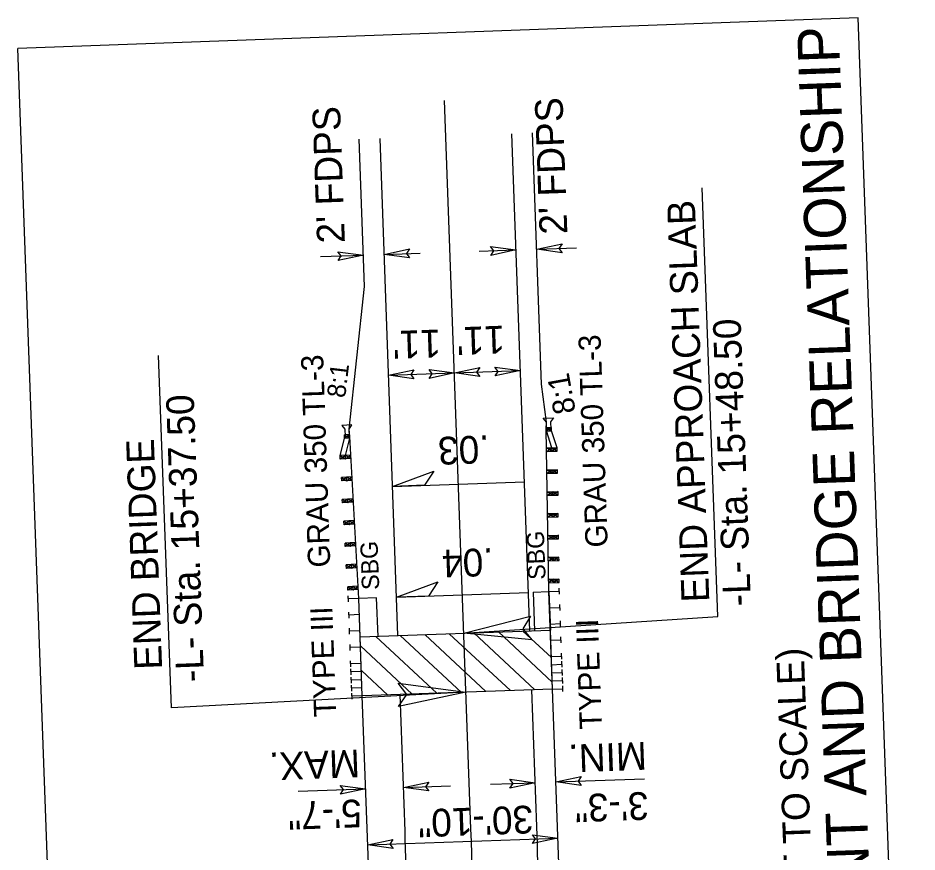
# Model space of a CAD drawing. Extents: x 2065068 to 2066582, y 144283 to 146300.
# Drawn here: x 2065068.5 to 2065327.5, y 145473.9 to 145714.2 of the extents above; entities that cross this region are included whole.
import ezdxf

# ---------------------------------------------------------------- set-up
doc = ezdxf.new("R2010")
doc.units = 0
for name, color, linetype in [('Default', 7, 'Continuous'), ('Prop Approach Slab', 7, 'Continuous'), ('Prop Conc Shoulder Berm Gutter', 7, 'Continuous'), ('Prop Dimension', 7, 'Continuous'), ('Prop Dimension Text', 7, 'Continuous'), ('Prop EOT', 7, 'Continuous'), ('Prop Guardrail Anchor Unit CELL', 7, 'Continuous'), ('Prop Horizontal Alignment', 7, 'Continuous'), ('Prop Paved Shoulder', 7, 'Continuous'), ('Prop Roadway Bridge', 7, 'Continuous'), ('Prop Structure Anchor Unit CELL', 7, 'Continuous'), ('Prop Superelevation  Arrow CELL', 7, 'Continuous'), ('Prop Superelevation Label', 7, 'Continuous'), ('Prop Terminator CELL', 7, 'Continuous')]:
    doc.layers.add(name, color=color, linetype=linetype)

# ---------------------------------------------------------------- blocks, each defined once
blk = doc.blocks.new('Super Arrow Terminator')
at = {"layer": 'Prop Superelevation  Arrow CELL'}
blk.add_lwpolyline([(0, 0), (-6, -2), (-4.625, 0)], close=True, dxfattribs=at)

msp = doc.modelspace()

# ---------------------------------------------------------------- linework, layer by layer
at = {"layer": 'Prop Approach Slab'}
for p, q in [((2065167.07, 145535.87), (2065221.87, 145537.86)), ((2065167.69, 145518.89), (2065167.07, 145535.87)), ((2065189.16, 145519.66), (2065171.56, 145536.04)), ((2065196.23, 145519.92), (2065178.62, 145536.29)), ((2065203.29, 145520.17), (2065185.69, 145536.55)), ((2065210.36, 145520.43), (2065192.76, 145536.8)), ((2065217.43, 145520.68), (2065199.82, 145537.06)), ((2065222.41, 145522.88), (2065206.89, 145537.31)), ((2065222.16, 145529.94), (2065213.96, 145537.57)), ((2065222.48, 145520.87), (2065221.87, 145537.86)), ((2065182.09, 145519.41), (2065167.17, 145533.29)), ((2065175.03, 145519.15), (2065167.42, 145526.23))]:
    msp.add_line(p, q, dxfattribs=at)
at = {"layer": 'Prop Dimension'}
for p, q in [((2065310.61, 145714.2), (2065068.47, 145705.45)), ((2065327.53, 145246.04), (2065310.61, 145714.2)), ((2065085.39, 145237.28), (2065068.47, 145705.45)), ((2065201.4, 145646.99), (2065211.97, 145647.37)), ((2065217.97, 145647.59), (2065229.45, 145648)), ((2065155.61, 145645.45), (2065168, 145645.89)), ((2065173.99, 145646.11), (2065184.39, 145646.49)), ((2065175.25, 145611.26), (2065213.23, 145612.63)), ((2065223.45, 145494.11), (2065248.97, 145495.03)), ((2065149.17, 145491.42), (2065168.65, 145492.13)), ((2065179.54, 145492.52), (2065193.06, 145493.01)), ((2065204.61, 145493.43), (2065217.52, 145493.89)), ((2065169.24, 145475.95), (2065224.04, 145477.93))]:
    msp.add_line(p, q, dxfattribs=at)
for points in [[(2065196.95, 145536.95), (2065270.11, 145541.76), (2065265.64, 145665.24)], [(2065197.56, 145519.97), (2065112.67, 145515.48), (2065109, 145616.96)]]:
    msp.add_lwpolyline(points, dxfattribs=at)
at = {"layer": 'Prop EOT'}
for p, q in [((2065215.94, 145537.64), (2065210.76, 145680.87)), ((2065177.96, 145536.27), (2065172.79, 145679.5)), ((2065217.98, 145481.27), (2065216.55, 145520.65)), ((2065180, 145479.89), (2065178.58, 145519.28))]:
    msp.add_line(p, q, dxfattribs=at)
for radius, start in [(809, 359.19567), (771, 359.05386)]:
    msp.add_arc((2064409.5, 145452.04), radius, start, 2.07024, dxfattribs=at)
at = {"layer": 'Prop Guardrail Anchor Unit CELL'}
for p, q in [((2065219.82, 145598.94), (2065222.76, 145599.05)), ((2065220.72, 145597.8), (2065219.82, 145598.94)), ((2065220.79, 145595.75), (2065220.72, 145597.8)), ((2065222.76, 145599.05), (2065221.94, 145597.84)), ((2065221.94, 145597.84), (2065222.01, 145595.79)), ((2065164.71, 145596.95), (2065161.77, 145596.84)), ((2065161.77, 145596.84), (2065162.67, 145595.7)), ((2065162.67, 145595.7), (2065162.75, 145593.65)), ((2065163.89, 145595.74), (2065164.71, 145596.95)), ((2065163.97, 145593.7), (2065163.89, 145595.74)), ((2065220.71, 145596.22), (2065222.21, 145596.24)), ((2065220.71, 145596.22), (2065222.22, 145595.24)), ((2065221.47, 145548.97), (2065220.71, 145595.72)), ((2065222.21, 145596.24), (2065220.72, 145595.22)), ((2065220.72, 145595.22), (2065222.22, 145595.24)), ((2065222.33, 145590.34), (2065220.72, 145595.22)), ((2065221.4, 145595.77), (2065220.79, 145595.75)), ((2065222.01, 145595.79), (2065221.4, 145595.77)), ((2065222.22, 145595.24), (2065222.21, 145596.24)), ((2065222.22, 145595.24), (2065222.21, 145595.74)), ((2065223.86, 145590.37), (2065222.22, 145595.24)), ((2065161.29, 145588.11), (2065162.58, 145593.09)), ((2065164.02, 145594.17), (2065162.52, 145594.09)), ((2065162.58, 145593.09), (2065162.52, 145594.09)), ((2065162.52, 145594.09), (2065164.08, 145593.17)), ((2065162.58, 145593.09), (2065162.55, 145593.59)), ((2065164.02, 145594.17), (2065162.58, 145593.09)), ((2065164.08, 145593.17), (2065162.58, 145593.09)), ((2065162.75, 145593.65), (2065163.36, 145593.67)), ((2065162.82, 145588.19), (2065164.08, 145593.17)), ((2065163.36, 145593.67), (2065163.97, 145593.7)), ((2065166.67, 145546.99), (2065164.05, 145593.67)), ((2065220.8, 145590.32), (2065223.86, 145590.37)), ((2065222.35, 145589.34), (2065220.8, 145590.32)), ((2065220.82, 145589.32), (2065222.33, 145590.34)), ((2065222.35, 145589.34), (2065222.33, 145590.34)), ((2065222.33, 145590.34), (2065223.88, 145589.37)), ((2065223.86, 145590.37), (2065222.35, 145589.34)), ((2065223.88, 145589.37), (2065223.86, 145590.37)), ((2065164.35, 145588.28), (2065161.29, 145588.11)), ((2065161.35, 145587.11), (2065161.29, 145588.11)), ((2065161.29, 145588.11), (2065162.88, 145587.19)), ((2065162.82, 145588.19), (2065161.35, 145587.11)), ((2065164.41, 145587.28), (2065161.35, 145587.11)), ((2065162.88, 145587.19), (2065162.82, 145588.19)), ((2065164.41, 145587.28), (2065162.82, 145588.19)), ((2065162.88, 145587.19), (2065164.35, 145588.28)), ((2065220.82, 145589.32), (2065223.88, 145589.37)), ((2065220.9, 145584.02), (2065223.9, 145584.07)), ((2065222.42, 145583.04), (2065220.9, 145584.02)), ((2065220.92, 145583.02), (2065222.4, 145584.04)), ((2065220.92, 145583.02), (2065223.92, 145583.07)), ((2065222.42, 145583.04), (2065222.4, 145584.04)), ((2065222.4, 145584.04), (2065223.92, 145583.07)), ((2065223.9, 145584.07), (2065222.42, 145583.04)), ((2065223.92, 145583.07), (2065223.9, 145584.07)), ((2065164.7, 145581.99), (2065161.71, 145581.82)), ((2065161.77, 145580.82), (2065161.71, 145581.82)), ((2065161.71, 145581.82), (2065163.26, 145580.9)), ((2065163.21, 145581.9), (2065161.77, 145580.82)), ((2065164.76, 145580.99), (2065161.77, 145580.82)), ((2065163.26, 145580.9), (2065163.21, 145581.9)), ((2065164.76, 145580.99), (2065163.21, 145581.9)), ((2065163.26, 145580.9), (2065164.7, 145581.99)), ((2065221, 145577.72), (2065224.14, 145577.77)), ((2065222.59, 145576.74), (2065221, 145577.72)), ((2065221.02, 145576.72), (2065222.57, 145577.74)), ((2065222.59, 145576.74), (2065222.57, 145577.74)), ((2065222.57, 145577.74), (2065224.16, 145576.77)), ((2065224.14, 145577.77), (2065222.59, 145576.74)), ((2065224.16, 145576.77), (2065224.14, 145577.77)), ((2065165.06, 145575.69), (2065161.93, 145575.52)), ((2065161.98, 145574.52), (2065161.93, 145575.52)), ((2065161.93, 145575.52), (2065163.55, 145574.61)), ((2065163.49, 145575.61), (2065161.98, 145574.52)), ((2065165.11, 145574.7), (2065161.98, 145574.52)), ((2065163.55, 145574.61), (2065163.49, 145575.61)), ((2065165.11, 145574.7), (2065163.49, 145575.61)), ((2065163.55, 145574.61), (2065165.06, 145575.69)), ((2065221.02, 145576.72), (2065224.16, 145576.77)), ((2065165.41, 145569.4), (2065162.38, 145569.23)), ((2065162.44, 145568.23), (2065162.38, 145569.23)), ((2065162.38, 145569.23), (2065163.95, 145568.32)), ((2065163.9, 145569.32), (2065162.44, 145568.23)), ((2065163.95, 145568.32), (2065163.9, 145569.32)), ((2065165.47, 145568.4), (2065163.9, 145569.32)), ((2065163.95, 145568.32), (2065165.41, 145569.4)), ((2065165.47, 145568.4), (2065165.41, 145569.4)), ((2065221.11, 145571.42), (2065224.14, 145571.47)), ((2065221.12, 145570.42), (2065221.11, 145571.42)), ((2065222.64, 145570.44), (2065221.11, 145571.42)), ((2065221.12, 145570.42), (2065222.62, 145571.44)), ((2065221.12, 145570.42), (2065224.16, 145570.47)), ((2065222.64, 145570.44), (2065222.62, 145571.44)), ((2065222.62, 145571.44), (2065224.16, 145570.47)), ((2065224.14, 145571.47), (2065222.64, 145570.44)), ((2065224.16, 145570.47), (2065224.14, 145571.47)), ((2065165.47, 145568.4), (2065162.44, 145568.23)), ((2065221.21, 145565.12), (2065224.26, 145565.17)), ((2065222.75, 145564.14), (2065221.21, 145565.12)), ((2065221.22, 145564.12), (2065222.73, 145565.14)), ((2065221.22, 145564.12), (2065224.27, 145564.17)), ((2065222.75, 145564.14), (2065222.73, 145565.14)), ((2065222.73, 145565.14), (2065224.27, 145564.17)), ((2065224.26, 145565.17), (2065222.75, 145564.14)), ((2065224.27, 145564.17), (2065224.26, 145565.17)), ((2065165.77, 145563.11), (2065162.72, 145562.94)), ((2065162.78, 145561.94), (2065162.72, 145562.94)), ((2065162.72, 145562.94), (2065164.3, 145562.03)), ((2065164.24, 145563.03), (2065162.78, 145561.94)), ((2065165.82, 145562.11), (2065162.78, 145561.94)), ((2065164.3, 145562.03), (2065164.24, 145563.03)), ((2065165.82, 145562.11), (2065164.24, 145563.03)), ((2065164.3, 145562.03), (2065165.77, 145563.11)), ((2065221.31, 145558.82), (2065224.36, 145558.87)), ((2065222.85, 145557.84), (2065221.31, 145558.82)), ((2065221.33, 145557.82), (2065222.84, 145558.84)), ((2065222.85, 145557.84), (2065222.84, 145558.84)), ((2065222.84, 145558.84), (2065224.38, 145557.87)), ((2065224.36, 145558.87), (2065222.85, 145557.84)), ((2065224.38, 145557.87), (2065224.36, 145558.87)), ((2065166.12, 145556.82), (2065163.07, 145556.65)), ((2065163.13, 145555.65), (2065163.07, 145556.65)), ((2065163.07, 145556.65), (2065164.65, 145555.74)), ((2065164.59, 145556.74), (2065163.13, 145555.65)), ((2065164.65, 145555.74), (2065164.59, 145556.74)), ((2065166.17, 145555.82), (2065164.59, 145556.74)), ((2065164.65, 145555.74), (2065166.12, 145556.82)), ((2065221.33, 145557.82), (2065224.38, 145557.87)), ((2065166.17, 145555.82), (2065163.13, 145555.65)), ((2065221.41, 145552.52), (2065224.41, 145552.56)), ((2065221.41, 145552.52), (2065222.91, 145552.54)), ((2065221.43, 145551.52), (2065221.41, 145552.52)), ((2065222.93, 145551.54), (2065221.41, 145552.52)), ((2065222.91, 145552.54), (2065221.43, 145551.52)), ((2065221.43, 145551.52), (2065224.43, 145551.56)), ((2065222.93, 145551.54), (2065222.91, 145552.54)), ((2065222.91, 145552.54), (2065224.43, 145551.56)), ((2065224.41, 145552.56), (2065222.93, 145551.54)), ((2065224.43, 145551.56), (2065224.41, 145552.56)), ((2065166.47, 145550.53), (2065163.48, 145550.36)), ((2065163.53, 145549.36), (2065163.48, 145550.36)), ((2065163.48, 145550.36), (2065165.03, 145549.45)), ((2065164.97, 145550.45), (2065163.53, 145549.36)), ((2065166.53, 145549.53), (2065163.53, 145549.36)), ((2065166.47, 145550.53), (2065164.97, 145550.45)), ((2065165.03, 145549.45), (2065164.97, 145550.45)), ((2065164.97, 145550.45), (2065166.53, 145549.53)), ((2065165.03, 145549.45), (2065166.47, 145550.53)), ((2065166.53, 145549.53), (2065166.47, 145550.53))]:
    msp.add_line(p, q, dxfattribs=at)
at = {"layer": 'Prop Horizontal Alignment'}
msp.add_line((2065198.99, 145480.58), (2065191.4, 145690.43), dxfattribs=at)
msp.add_arc((2064409.5, 145452.04), 790, 357.89352, 2.07024, dxfattribs=at)
at = {"layer": 'Prop Paved Shoulder'}
for p, q in [((2065219.37, 145608.74), (2065216.76, 145681.09)), ((2065168.32, 145636.87), (2065166.79, 145679.28)), ((2065163.89, 145595.74), (2065168.32, 145636.87)), ((2065220.72, 145597.8), (2065219.37, 145608.74)), ((2065220.71, 145595.72), (2065220.72, 145597.8)), ((2065164.05, 145593.67), (2065163.89, 145595.74)), ((2065221.47, 145548.97), (2065220.71, 145595.72)), ((2065166.67, 145546.99), (2065164.05, 145593.67)), ((2065216.88, 145548.81), (2065221.47, 145548.97)), ((2065216.88, 145548.81), (2065217.28, 145537.69)), ((2065221.47, 145548.97), (2065221.87, 145537.86)), ((2065171.81, 145547.18), (2065166.67, 145546.99)), ((2065167.07, 145535.87), (2065166.67, 145546.99)), ((2065172.21, 145536.06), (2065171.81, 145547.18))]:
    msp.add_line(p, q, dxfattribs=at)
at = {"layer": 'Prop Roadway Bridge'}
for p, q in [((2065222.48, 145520.87), (2065167.69, 145518.89)), ((2065225.37, 145440.94), (2065222.48, 145520.87)), ((2065170.58, 145438.96), (2065167.69, 145518.89))]:
    msp.add_line(p, q, dxfattribs=at)
at = {"layer": 'Prop Structure Anchor Unit CELL'}
for p, q in [((2065221.47, 145548.97), (2065224.47, 145549.08)), ((2065222.48, 145520.87), (2065221.47, 145548.97)), ((2065224.5, 145548.22), (2065224.44, 145549.94)), ((2065163.7, 145546.03), (2065163.64, 145547.74)), ((2065166.67, 145546.99), (2065163.67, 145546.88)), ((2065167.69, 145518.89), (2065166.67, 145546.99)), ((2065221.64, 145544.29), (2065224.64, 145544.4)), ((2065224.67, 145543.54), (2065224.6, 145545.26)), ((2065163.87, 145541.34), (2065163.81, 145543.06)), ((2065166.84, 145542.31), (2065163.84, 145542.2)), ((2065164.04, 145536.66), (2065163.98, 145538.37)), ((2065221.81, 145539.6), (2065224.81, 145539.71)), ((2065224.84, 145538.85), (2065224.77, 145540.57)), ((2065167.01, 145537.62), (2065164.01, 145537.52)), ((2065225.01, 145534.17), (2065224.94, 145535.89)), ((2065164.21, 145531.97), (2065164.15, 145533.69)), ((2065167.18, 145532.94), (2065164.18, 145532.83)), ((2065221.98, 145534.92), (2065224.97, 145535.03)), ((2065222.15, 145530.24), (2065225.14, 145530.34)), ((2065225.17, 145529.49), (2065225.11, 145531.2)), ((2065164.38, 145527.29), (2065164.32, 145529)), ((2065167.35, 145528.25), (2065164.35, 145528.15)), ((2065222.23, 145527.89), (2065225.23, 145528)), ((2065225.26, 145527.14), (2065225.2, 145528.86)), ((2065164.47, 145524.95), (2065164.4, 145526.66)), ((2065167.43, 145525.91), (2065164.43, 145525.8)), ((2065222.32, 145525.55), (2065225.31, 145525.66)), ((2065225.34, 145524.8), (2065225.28, 145526.52)), ((2065164.55, 145522.6), (2065164.49, 145524.32)), ((2065167.52, 145523.57), (2065164.52, 145523.46)), ((2065222.4, 145523.21), (2065225.4, 145523.32)), ((2065225.43, 145522.46), (2065225.37, 145524.18)), ((2065164.64, 145520.26), (2065164.57, 145521.98)), ((2065167.6, 145521.23), (2065164.6, 145521.12)), ((2065222.48, 145520.87), (2065225.48, 145520.98)), ((2065225.51, 145520.12), (2065225.45, 145521.83)), ((2065164.72, 145517.92), (2065164.66, 145519.64)), ((2065167.69, 145518.89), (2065164.69, 145518.78))]:
    msp.add_line(p, q, dxfattribs=at)
at = {"layer": 'Prop Superelevation  Arrow CELL'}
for p, q in [((2065176.41, 145579.23), (2065214.39, 145580.6)), ((2065177.56, 145547.33), (2065215.54, 145548.71))]:
    msp.add_line(p, q, dxfattribs=at)
at = {"layer": 'Prop Terminator CELL'}
for points in [[(2065160.67, 145646.88), (2065168, 145645.89), (2065160.72, 145644.33), (2065161.6, 145645.66)], [(2065181.32, 145645.12), (2065173.99, 145646.11), (2065181.27, 145647.67), (2065180.39, 145646.34)], [(2065204.64, 145648.36), (2065211.97, 145647.37), (2065204.69, 145645.81), (2065205.58, 145647.14)], [(2065225.3, 145646.59), (2065217.97, 145647.59), (2065225.25, 145649.15), (2065224.36, 145647.82)], [(2065201.57, 145610.95), (2065194.24, 145611.94), (2065201.52, 145613.5), (2065200.63, 145612.17)], [(2065205.9, 145613.62), (2065213.23, 145612.63), (2065205.95, 145611.07), (2065206.83, 145612.4)], [(2065182.58, 145610.26), (2065175.25, 145611.26), (2065182.53, 145612.82), (2065181.65, 145611.49)], [(2065186.91, 145612.93), (2065194.24, 145611.94), (2065186.96, 145610.38), (2065187.84, 145611.71)], [(2065216.58, 145535.03), (2065196.95, 145536.95), (2065216.19, 145541.83), (2065213.97, 145538.2)], [(2065178.02, 145522.61), (2065197.56, 145519.97), (2065178.15, 145515.81), (2065180.51, 145519.35)], [(2065186.87, 145491.53), (2065179.54, 145492.52), (2065186.82, 145494.08), (2065185.94, 145492.75)], [(2065210.19, 145494.88), (2065217.52, 145493.89), (2065210.24, 145492.33), (2065211.12, 145493.66)], [(2065230.78, 145493.12), (2065223.45, 145494.11), (2065230.73, 145495.67), (2065229.85, 145494.34)], [(2065161.32, 145493.12), (2065168.65, 145492.13), (2065161.38, 145490.57), (2065162.26, 145491.9)], [(2065216.71, 145478.92), (2065224.04, 145477.93), (2065216.76, 145476.37), (2065217.64, 145477.7)], [(2065176.57, 145474.95), (2065169.24, 145475.95), (2065176.52, 145477.51), (2065175.63, 145476.18)]]:
    msp.add_lwpolyline(points, close=True, dxfattribs=at)

# ---------------------------------------------------------------- block references
at = {"layer": 'Prop Superelevation  Arrow CELL', "xscale": 1.999996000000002, "yscale": 1.999996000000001, "rotation": -177.9297555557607}
for p in [(2065176.41, 145579.23), (2065177.56, 145547.33)]:
    msp.add_blockref('Super Arrow Terminator', p, dxfattribs=at)

# ---------------------------------------------------------------- texts
at = {"layer": 'Default'}
for height, rotation, p in [(5.291, 83.1952, (2065162.73, 145604.58)), (6.349, 100.2886, (2065229.23, 145600.67))]:
    msp.add_text('8:1', height=height, rotation=rotation, dxfattribs=at).set_placement(p)
at = {"layer": 'Prop Conc Shoulder Berm Gutter'}
for p in [(2065220.52, 145552.44), (2065172.59, 145549.52)]:
    msp.add_text('SBG', height=5, rotation=92.0702, dxfattribs=at).set_placement(p)
at = {"layer": 'Prop Dimension'}
for s, height, p in [('DETAIL SHOWING PAVEMENT AND BRIDGE RELATIONSHIP', 12, (2065321.51, 145254.04)), ('END APPROACH SLAB', 8, (2065267.69, 145546.01)), ('-L- Sta. 15+48.50', 8, (2065279.68, 145544.83)), ('-L- Sta. 15+37.50', 8, (2065122.1, 145522.98)), ('END BRIDGE', 8, (2065110.02, 145526.58)), ('(NOT TO SCALE)', 8, (2065297.98, 145447.37))]:
    msp.add_text(s, height=height, rotation=92.0702, dxfattribs=at).set_placement(p)
at = {"layer": 'Prop Dimension Text'}
for s, rotation, p in [("2' FDPS", 92.0702, (2065226.79, 145651.98)), ("2' FDPS", 92.0702, (2065162.68, 145649.43)), ("11'", 182.0702, (2065190.17, 145624.48)), ("11'", 182.0702, (2065208.62, 145625.58)), ('MIN.', 182.0702, (2065249.52, 145505.65)), ('MAX.', 182.0702, (2065166.86, 145503.48)), ('5\'-7"', 182.0702, (2065167.38, 145489.09)), ('3\'-3"', 182.0702, (2065250.04, 145491.26)), ('30\'-10"', 182.0702, (2065216.78, 145487.35))]:
    msp.add_text(s, height=8, rotation=rotation, dxfattribs=at).set_placement(p)
at = {"layer": 'Prop Guardrail Anchor Unit CELL'}
for p in [(2065238.42, 145561.77), (2065158.48, 145556)]:
    msp.add_text('GRAU 350 TL-3', height=6.4, rotation=91.9475, dxfattribs=at).set_placement(p)
at = {"layer": 'Prop Structure Anchor Unit CELL'}
for p in [(2065160.2, 145512.92), (2065236.76, 145509.39)]:
    msp.add_text('TYPE III', height=6.4, rotation=92.0702, dxfattribs=at).set_placement(p)
at = {"layer": 'Prop Superelevation Label'}
for s, p in [('.03', (2065204.22, 145594)), ('.04', (2065205.37, 145561.51))]:
    msp.add_text(s, height=8, rotation=182.0702, dxfattribs=at).set_placement(p)

doc.saveas('drawing.dxf')
